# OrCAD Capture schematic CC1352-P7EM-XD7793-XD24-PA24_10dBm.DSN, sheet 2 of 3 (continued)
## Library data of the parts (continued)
L14 L52 L61 = INDUCTOR_HOR_1_2: INDUCTOR, RF, CHIP, NON-MAGNETIC CORE, 2nH, -0.3nH/+0.3nH, 0.3A, -55DEGC/+125DEGC, 0402, SMD; Additional Datasheet URL: https://search.murata.co.jp/Ceramy/image/img/P02/JELF243B-0010.pdf; AutoDoc File: https://notefied-dynamic-precision.com/DB/Apps/Desktop/Item/Object.aspx?id=113364; BU Name: TEXAS INSTRUMENTS NORWAY; Budget Currency: EUR; Budget Price: 0.031; Budgetary Price: 0.01872 USD; Client Status: UNDER_REVIEW; Core Material: NON-MAGNETIC; Country of Origin: Japan,Singapore; Datasheet URL: https://www.murata.com/-/media/webrenewal/support/library/catalog/products/inductor/chip/o05e.ashx?la=en-gb; Datasheet URL 1: http://psearch.murata.com/inductor/product/LQG15HS2N0S02%23.pdf; Datasheet URL 2: http://www.murata.com/~/media/webrenewal/support/library/catalog/products/inductor/chip/o05e.ashx; Exclusive for Customers: TEXAS INSTRUMENTS NORWAY; Frequency: 6GHz; Lead Time: 8; Mass: 0.001g; Max Oper Temp: +125DEGC; Max Tol: +0.3nH; Maximum Operating Temperature: +125DEGC; Maximum Tolerance: +0.3nH; Min Oper Temp: -55DEGC; Min Tol: -0.3nH; Minimum Operating Temperature: -55DEGC; Minimum Tolerance: -0.3nH; Mounting Type: SMD; NOTEfied URL: https://notefied-dynamic-precision.com/NOTEfiedWebInterface/part/show?partNumber=03-07527; Notes: Standard item: Duplicate Reason: custom footprint for TEXAS INSTRUMENTS NORWAY.; PCB Package: 0402; Packing Size: 10000; Packing Type: Tape & Reel; Part Number: 03-07527; Part Type: Inductor|RF|CHIP|0402; REACH/SVHC Compliance: Compliant; REACH/SVHC Details: SVHC List Version Jul 7, 2017; REACH/SVHC Source: REACH Declaration; REACH/SVHC Status: Unaffected; REACH/SVHC_COMPLIANCE: COMPLIANT; REACH/SVHC_DETAILS: SVHC LIST VERSION Dec 17, 2015; REACH/SVHC_SOURCE: REACH DECLARATION; REACH/SVHC_STATUS: UNAFFECTED; ROHS: Compliant; Revision: R023; RoHS Status: ROHS_COMPLIANT; Rtd Current: 0.3A; Status: Released; Texas Part Status: Under Review; Type: Inductor; Vendor: MURATA; Vendor Part Number: LQG15HS2N0S02D; Vendor Part Status: Active; Weight: 0.001g
L31 L41 = INDUCTOR_HOR_1_2: INDUCTOR, RF, CHIP, NON-MAGNETIC CORE, 3.9nH, -0.3nH/+0.3nH, 0.3A, -55DEGC/+125DEGC, 0402, SMD; ALT_SYMBOLS: INDC1005X60C2L,INDC1005X60C2M; Additional Datasheet URL: https://search.murata.co.jp/Ceramy/image/img/P02/JELF243B-0010.pdf; Budgetary Price: 0.01872 USD; Country of Origin: Japan,Singapore; Datasheet URL: https://www.murata.com/-/media/webrenewal/support/library/catalog/products/inductor/chip/o05e.ashx?la=en-gb; FPLIST: INDC1005X60C2N,INDC1005X60D2N; Frequency: 6GHz; Lead Time: 8; Mass: 0.001g; Maximum Operating Temperature: +125DEGC; Maximum Tolerance: +0.3nH; Minimum Operating Temperature: -55DEGC; Minimum Tolerance: -0.3nH; Mounting Type: SMD; NOTEfied URL: https://notefied-dynamic-precision.com/NOTEfiedWebInterface/part/show?partNumber=03-06630; PCB Package: 0402; Packing Size: 10000; Packing Type: Tape & Reel; Part Number: 03-06630; Part Type: Inductor|RF|CHIP|0402; REACH/SVHC Compliance: Compliant; REACH/SVHC Details: SVHC List Version Jul 7, 2017; REACH/SVHC Source: REACH Declaration; REACH/SVHC Status: Unaffected; ROHS: Compliant; Resistance: 0.18; Revision: R022; Status: Released; Texas Part Status: Under Review; Type: Inductor; Vendor: MURATA; Vendor Part Number: LQG15HS3N9S02D; Vendor Part Status: Active
L32 = INDUCTOR_HOR_1_2: INDUCTOR, RF, CHIP, NON-MAGNETIC CORE, 22nH, -5%/+5%, 0.3A, -55DEGC/+125DEGC, 0402, SMD; Additional Datasheet URL: https://search.murata.co.jp/Ceramy/image/img/P02/JELF243B-0010.pdf; AutoDoc File: https://notefied-dynamic-precision.com/DB/Apps/Desktop/Item/Object.aspx?id=113365; BU Name: TEXAS INSTRUMENTS NORWAY; Budget Currency: EUR; Budget Price: 0.03; Budgetary Price: 0.01872 USD; Client Status: UNDER_REVIEW; Core Material: NON-MAGNETIC; Country of Origin: Japan,Singapore; Datasheet URL: https://www.murata.com/-/media/webrenewal/support/library/catalog/products/inductor/chip/o05e.ashx?la=en-gb; Datasheet URL 1: http://psearch.murata.com/inductor/product/LQG15HS27NJ02%23.pdf; Datasheet URL 2: http://www.murata.com/~/media/webrenewal/support/library/catalog/products/inductor/chip/o05e.ashx; Exclusive for Customers: TEXAS INSTRUMENTS NORWAY; Frequency: 1900MHz; Lead Time: 8; Mass: 0.001g; Max Oper Temp: +125DEGC; Max Tol: +5%; Maximum Operating Temperature: +125DEGC; Maximum Tolerance: +5%; Min Oper Temp: -55DEGC; Min Tol: -5%; Minimum Operating Temperature: -55DEGC; Minimum Tolerance: -5%; Mounting Type: SMD; NOTEfied URL: https://notefied-dynamic-precision.com/NOTEfiedWebInterface/part/show?partNumber=03-07529; Notes: Standard item: Duplicate Reason: custom footprint for TEXAS INSTRUMENTS NORWAY.; PCB Package: 0402; Packing Size: 10000; Packing Type: Tape & Reel; Part Number: 03-07529; Part Type: Inductor|RF|CHIP|0402; REACH/SVHC Compliance: Compliant; REACH/SVHC Details: SVHC List Version Jul 7, 2017; REACH/SVHC Source: REACH Declaration; REACH/SVHC Status: Unaffected; REACH/SVHC_COMPLIANCE: COMPLIANT; REACH/SVHC_DETAILS: SVHC LIST VERSION Dec 17, 2015; REACH/SVHC_SOURCE: REACH DECLARATION; REACH/SVHC_STATUS: UNAFFECTED; ROHS: Compliant; Revision: R022; RoHS Status: ROHS_COMPLIANT; Rtd Current: 0.3A; Status: Released; Texas Part Status: Under Review; Type: Inductor; Vendor: MURATA; Vendor Part Number: LQG15HS22NJ02D; Vendor Part Status: Active; Weight: 0.001g
L33 L42 = INDUCTOR_HOR_1_2: INDUCTOR, RF, CHIP, NON-MAGNETIC CORE, 10nH, -5%/+5%, 0.3A, -55DEGC/+125DEGC, 0402, SMD; ALT_SYMBOLS: INDC1005X60C2L,INDC1005X60C2M; Additional Datasheet URL: https://search.murata.co.jp/Ceramy/image/img/P02/JELF243B-0010.pdf; AutoDoc File: https://notefied-dynamic-precision.com/DB/Apps/Desktop/Item/Object.aspx?id=113370; BU Name: TEXAS INSTRUMENTS NORWAY; Budget Currency: EUR; Budget Price: 0.03; Budgetary Price: 0.01872 USD; Client Status: UNDER_REVIEW; Core Material: NON-MAGNETIC; Country of Origin: Japan,Singapore; Datasheet URL: https://www.murata.com/-/media/webrenewal/support/library/catalog/products/inductor/chip/o05e.ashx?la=en-gb; Datasheet URL 1: http://psearch.murata.com/inductor/product/LQG15HS7N5J02%23.pdf; Datasheet URL 2: http://www.murata.com/~/media/webrenewal/support/library/catalog/products/inductor/chip/o05e.ashx; FPLIST: INDC1005X60C2N,INDC1005X60D2N; Frequency: 3.4GHz; Lead Time: 8; Mass: 0.001g; Max Oper Temp: +125DEGC; Max Tol: +5%; Maximum Operating Temperature: +125DEGC; Maximum Tolerance: +5%; Min Oper Temp: -55DEGC; Min Tol: -5%; Minimum Operating Temperature: -55DEGC; Minimum Tolerance: -5%; Mounting Type: SMD; NOTEfied URL: https://notefied-dynamic-precision.com/NOTEfiedWebInterface/part/show?partNumber=03-06635; PCB Package: 0402; Packing Size: 10000; Packing Type: Tape & Reel; Part Number: 03-06635; Part Type: Inductor|RF|CHIP|0402; REACH/SVHC Compliance: Compliant; REACH/SVHC Details: SVHC List Version Jul 7, 2017; REACH/SVHC Source: REACH Declaration; REACH/SVHC Status: Unaffected; REACH/SVHC_COMPLIANCE: COMPLIANT; REACH/SVHC_DETAILS: SVHC LIST VERSION Dec 17, 2015; REACH/SVHC_SOURCE: REACH DECLARATION; REACH/SVHC_STATUS: UNAFFECTED; ROHS: Compliant; Resistance: 0.26; Revision: R021; RoHS Status: ROHS_COMPLIANT; Rtd Current: 0.3A; Status: Released; Texas Part Status: Under Review; Type: Inductor; Vendor: MURATA; Vendor Part Number: LQG15HS10NJ02D; Vendor Part Status: Active; Weight: 0.001g
L34 = INDUCTOR_HOR_1_2: INDUCTOR, RF, CHIP, NON-MAGNETIC CORE, 7.5nH, -5%/+5%, 0.3A, -55DEGC/+125DEGC, 0402, SMD; Additional Datasheet URL: https://search.murata.co.jp/Ceramy/image/img/P02/JELF243B-0010.pdf; AutoDoc File: https://notefied-dynamic-precision.com/DB/Apps/Desktop/Item/Object.aspx?id=113369; BU Name: TEXAS INSTRUMENTS NORWAY; Budget Currency: EUR; Budget Price: 0.03; Budgetary Price: 0.01872 USD; Client Status: UNDER_REVIEW; Core Material: NON-MAGNETIC; Country of Origin: Missing Info; Datasheet URL: https://www.murata.com/-/media/webrenewal/support/library/catalog/products/inductor/chip/o05e.ashx?la=en-gb; Datasheet URL 1: http://psearch.murata.com/inductor/product/LQG15HS6N8J02%23.pdf; Datasheet URL 2: http://www.murata.com/~/media/webrenewal/support/library/catalog/products/inductor/chip/o05e.ashx; Frequency: 4.2GHz; Lead Time: 8; Mass: 0.001g; Max Oper Temp: +125DEGC; Max Tol: +5%; Maximum Operating Temperature: +125DEGC; Maximum Tolerance: +5%; Min Oper Temp: -55DEGC; Min Tol: -5%; Minimum Operating Temperature: -55DEGC; Minimum Tolerance: -5%; Mounting Type: SMD; NOTEfied URL: https://notefied-dynamic-precision.com/NOTEfiedWebInterface/part/show?partNumber=03-07022; PCB Package: 0402; Packing Size: 10000; Packing Type: Tape & Reel; Part Number: 03-07022; Part Type: Inductor|RF|CHIP|0402; REACH/SVHC Compliance: Compliant; REACH/SVHC Details: SVHC List Version Jul 7, 2017; REACH/SVHC Source: REACH Declaration; REACH/SVHC Status: Unaffected; REACH/SVHC_COMPLIANCE: COMPLIANT; REACH/SVHC_DETAILS: SVHC LIST VERSION Dec 17, 2015; REACH/SVHC_SOURCE: REACH DECLARATION; REACH/SVHC_STATUS: UNAFFECTED; ROHS: Compliant; Resistance: 0.24; Revision: R023; RoHS Status: ROHS_COMPLIANT; Rtd Current: 0.3A; Status: Released; Texas Part Status: Under Review; Type: Inductor; Vendor: MURATA; Vendor Part Number: LQG15HS7N5J02D; Vendor Part Status: Active; Weight: 0.001g
L53 = INDUCTOR_HOR_1_2: INDUCTOR, RF, NON-MAGNETIC CORE, 1.6nH, -0.3nH/+0.3nH, 1A, -55DEGC/+125DEGC, 0402, SMD; Additional Datasheet URL: https://search.murata.co.jp/Ceramy/image/img/P02/JELF243B-0010.pdf; AutoDoc File: https://notefied-dynamic-precision.com/DB/Apps/Desktop/Item/Object.aspx?id=116101; BU Name: TEXAS INSTRUMENTS NORWAY; Budget Currency: EUR; Budget Price: 0.031; Budgetary Price: 0.01872 USD; Client Status: UNDER_REVIEW; Core Material: NON-MAGNETIC; Datasheet URL: https://www.murata.com/-/media/webrenewal/support/library/catalog/products/inductor/chip/o05e.ashx?la=en-gb; Datasheet URL 1: http://psearch.murata.com/inductor/product/LQG15HS1N8S02%23.pdf; Datasheet URL 2: http://www.murata.com/~/media/webrenewal/support/library/catalog/products/inductor/chip/o05e.ashx; Frequency: 6GHz; Lead Time: 8; Mass: 0.001g; Max Oper Temp: +125DEGC; Max Tol: +0.3nH; Maximum Operating Temperature: +125DEGC; Maximum Tolerance: +0.3nH; Min Oper Temp: -55DEGC; Min Tol: -0.3nH; Minimum Operating Temperature: -55DEGC; Minimum Tolerance: -0.3nH; Mounting Type: SMD; NOTEfied URL: https://notefied-dynamic-precision.com/NOTEfiedWebInterface/part/show?partNumber=03-07865; PCB Package: 0402; Packing Size: 10000; Packing Type: Tape & Reel; Part Number: 03-07865; Part Type: Inductor|RF|CHIP|0402; REACH/SVHC Compliance: Compliant; REACH/SVHC Details: SVHC List Version Jul 7, 2017; REACH/SVHC Source: REACH Declaration; REACH/SVHC Status: Unaffected; REACH/SVHC_COMPLIANCE: COMPLIANT; REACH/SVHC_DETAILS: SVHC LIST VERSION Jun 20, 2016; REACH/SVHC_SOURCE: REACH DECLARATION; REACH/SVHC_STATUS: UNAFFECTED; ROHS: Compliant; Resistance: 0.07; Revision: R013; RoHS Status: ROHS_COMPLIANT; Rtd Current: 0.3A; Status: Released; Texas Part Status: Under Review; Type: Inductor; Vendor: MURATA; Vendor Part Number: LQG15HS1N6S02D; Vendor Part Status: Active; Weight: 0.001g
L54 = INDUCTOR_HOR_1_2: INDUCTOR, RF, CHIP, NON-MAGNETIC CORE, 1nH, -0.3nH/+0.3nH, 0.3A, -55DEGC/+125DEGC, 0402, SMD; ALT_SYMBOLS: INDC1005X60C2L,INDC1005X60C2M; Additional Datasheet URL: https://search.murata.co.jp/Ceramy/image/img/P02/JELF243B-0010.pdf; AutoDoc File: https://notefied-dynamic-precision.com/DB/Apps/Desktop/Item/Object.aspx?id=116041; BU Name: TEXAS INSTRUMENTS NORWAY; Budget Currency: EUR; Budget Price: 0.031; Budgetary Price: 0.01872 USD; Client Status: UNDER_REVIEW; Core Material: NON-MAGNETIC; Country of Origin: Japan,Singapore; Datasheet URL: https://www.murata.com/-/media/webrenewal/support/library/catalog/products/inductor/chip/o05e.ashx?la=en-gb; Datasheet URL 1: http://psearch.murata.com/inductor/product/LQG15HS1N0S02%23.pdf; Datasheet URL 2: http://www.murata.com/~/media/webrenewal/support/library/catalog/products/inductor/chip/o05e.ashx; Frequency: 10GHz; Lead Time: 8; Mass: 0.001g; Max Oper Temp: +125DEGC; Max Tol: +0.3nH; Maximum Operating Temperature: +125DEGC; Maximum Tolerance: +0.3nH; Min Oper Temp: -55DEGC; Min Tol: -0.3nH; Minimum Operating Temperature: -55DEGC; Minimum Tolerance: -0.3nH; Mounting Type: SMD; NOTEfied URL: https://notefied-dynamic-precision.com/NOTEfiedWebInterface/part/show?partNumber=03-07676; PCB Package: 0402; Packing Size: 10000; Packing Type: Tape & Reel; Part Number: 03-07676; Part Type: Inductor|RF|CHIP|0402; REACH/SVHC Compliance: Compliant; REACH/SVHC Details: SVHC List Version Jul 7, 2017; REACH/SVHC Source: REACH Declaration; REACH/SVHC Status: Unaffected; REACH/SVHC_COMPLIANCE: COMPLIANT; REACH/SVHC_DETAILS: SVHC LIST VERSION Jun 20, 2016; REACH/SVHC_SOURCE: REACH DECLARATION; REACH/SVHC_STATUS: UNAFFECTED; ROHS: Compliant; Resistance: 0.07; Revision: R024; RoHS Status: ROHS_COMPLIANT; Rtd Current: 0.3A; Status: Released; Texas Part Status: Under Review; Type: Inductor; Vendor: MURATA; Vendor Part Number: LQG15HS1N0S02D; Vendor Part Status: Active; Weight: 0.001g
L331 = INDUCTOR: INDUCTOR, STANDARD, FERRITE CORE, 6.8uH, -20%/+20%, 0.11A, -55DEGC/+125DEGC, 0805, SMD; ALT_SYMBOLS: INDC2012X150A2L,INDC2012X150A2M; Additional Datasheet URL: https://product.tdk.com/en/search/inductor/inductor/smd/info?part_no=MLZ2012N6R8LT000; AutoDoc File: https://notefied-dynamic-precision.com/DB/Apps/Desktop/Item/Object.aspx?id=102853; BU Name: DYNAMIC PRECISION GDANSK; Budget Currency: EUR; Budget Price: 0.059; Budgetary Price: 0.045 USD; Client Status: UNDER_REVIEW; Core Material: FERRITE; Country of Origin: Missing Info; Datasheet URL: http://product.tdk.com/info/en/catalog/datasheets/inductor_commercial_decoupling_mlz2012_en.pdf; Datasheet URL 1: https://product.tdk.com/info/en/catalog/datasheets/inductor_commercial_decoupling_mlz2012_en.pdf; Datasheet URL 2: N/A; Lead Time: 10; MPN: MLZ2012N6R8LT000; MPN Status: ACTIVE; Manufacturer: TDK; Mass: 0.01g; Max Oper Temp: +125DEGC; Max Tol: +20%; Maximum Operating Temperature: +125DEGC; Maximum Tolerance: +20%; Min Oper Temp: -55DEGC; Min Tol: -20%; Minimum Operating Temperature: -55DEGC; Minimum Tolerance: -20%; Mounting Type: SMD; NOTE Status: PREFERRED; NOTEfied URL: https://notefied-dynamic-precision.com/NOTEfiedWebInterface/part/show?partNumber=03-07266; Old Footprint: INDC2012X150N; PCB Package: 0805; Packing Size: 4000; Packing Type: Tape & Reel; Part Number: 03-07266; Part Type: Inductor|STANDARD|CHIP|0805; REACH/SVHC Compliance: Compliant; REACH/SVHC Details: SVHC List Version Jan 12, 2017; REACH/SVHC Source: REACH Declaration; REACH/SVHC Status: Unaffected; REACH/SVHC_COMPLIANCE: COMPLIANT; REACH/SVHC_DETAILS: SVHC LIST VERSION Dec 17, 2015; REACH/SVHC_SOURCE: REACH DECLARATION; REACH/SVHC_STATUS: UNAFFECTED; ROHS: Compliant; Resistance: 0.25; Revision: R019; RoHS Status: ROHS_COMPLIANT; Rtd Current: 1.1A; Status: Released; Texas Part Status: Under Review; Type: Inductor; Vendor: TDK; Vendor Part Number: MLZ2012N6R8LT000; Vendor Part Status: Active; WEIGHT: 0.01g
P1 P2 = CONN_HEADER_2X10_P_S: CONNECTOR, HEADER, FEMALE, STRAIGHT, 2 ROWS, 20 PINS, PITCH 1.27mm, SMD; ALT_SYMBOLS: SAMTEC_SFM11002AL,SAMTEC_SFM11002AM; Additional Datasheet URL: http://suddendocs.samtec.com/prints/sfm-1xx-xx-xxx-d-xxx-mkt.pdf; Alt IPC Footprints: SAMTEC_SFM11002AL,SAMTEC_SFM11002AM; AutoDoc File: https://notefied-dynamic-precision.com/DB/Apps/Desktop/Item/Object.aspx?id=85603; BU Name: TEXAS INSTRUMENTS NORWAY; Budget Currency: USD; Budget Price: 3.180; Budgetary Price: 5.3504 USD; CLASS: IO; Client Status: UNDER_REVIEW; Country of Origin: China,Costa Rica,Malaysia,Singapore,United States; Datasheet URL: http://suddendocs.samtec.com/catalog_english/sfm.pdf; Datasheet URL 1: http://suddendocs.samtec.com/catalog_english/sfm.pdf; Datasheet URL 2: http://suddendocs.samtec.com/prints/sfm-1xx-xx-xxx-d-xxx-mkt.pdf; MPN: SFM-110-02-SM-D-A-K-TR; MPN Status: ACTIVE; Manufacturer: SAMTEC; Mass: 0.30875g; Max Oper Temp: +125DEGC; Maximum Operating Temperature: +125DEGC; Min Oper Temp: -55DEGC; Minimum Operating Temperature: -55DEGC; Mounting Type: SMD; NOTE Status: PREFERRED; NOTEfied URL: https://notefied-dynamic-precision.com/NOTEfiedWebInterface/part/show?partNumber=06-02251; No Of Pos: 20; No Of Rows: 2; Number of Positions: 20; Number of Rows: 2; Packing Size: 725; Packing Type: Tape & Reel; Part Number: 06-02251; Part Type: Connector|HEADER|STANDARD; Pitch: 1.27mm; REACH/SVHC Compliance: Compliant; REACH/SVHC Details: SVHC List Version Jan 12, 2017; REACH/SVHC Source: Material Declaration; REACH/SVHC Status: Unaffected; ROHS: Compliant; Revision: R017; RoHS Status: ROHS_COMPLIANT; Status: Released; Texas Part Status: Under Review; Type: Connector; Vendor: SAMTEC; Vendor Part Number: SFM-110-02-SM-D-A-K-TR; Vendor Part Status: Active; Weight: 0.30875g
R1 R2 = RESISTOR: RESISTOR, THICK FILM, 0, 0R/+0.008R, 0.33W, 5A, -55DEGC/+155DEGC, 0603, SMD; ALT_SYMBOLS: RESC1608X55A2L,RESC1608X55A2M; Additional Datasheet URL: N/A; AutoDoc File: https://notefied-dynamic-precision.com/DB/Apps/Desktop/Item/Object.aspx?id=86391; BU Name: DYNAMIC PRECISION GDANSK; Budget Currency: EUR; Budget Price: 0.007; Budgetary Price: 0.034 EUR; Client Status: UNDER_REVIEW; Country of Origin: Israel; Datasheet URL: https://www.vishay.com/docs/20043/crcwhpe3.pdf; Datasheet URL 1: http://www.vishay.com/docs/20035/dcrcwe3.pdf; Datasheet URL 2: N/A; Definied Quality: INDUSTRIAL; Esd Level: N/A; Lead Time: 14; LifeCycle Status: ACTIVE; MPN: RESISTOR_0402_0_+/-5%_50V_0.063W_M_+/-200PPM; MPN Status: ACTIVE; MSL: N/A; MTBF: N/A; MTBF Standard: N/A; Manufacturer: MANUFACTURER SELECTION; Mass: 0.002g; Max Oper Temp: +155DEGC; Max TC: N/A; Max Tol: N/A; Maximum Operating Temperature: +155DEGC; Maximum Temperature Coefficient: N/A; Maximum Tolerance: +0.008R; Min Oper Temp: -55DEGC; Min TC: N/A; Min Tol: N/A; Minimum Operating Temperature: -55DEGC; Minimum Temperature Coeficient: N/A; Minimum Tolerance: 0R; Mounting Type: SMD; NOTE Status: PREFERRED; NOTEfied URL: https://notefied-dynamic-precision.com/NOTEfiedWebInterface/part/show?partNumber=01-16898; Old Footprint: RESC1005X40N; PCB Package: 0603; Packing Size: 5000; Packing Type: Tape & Reel; Part Number: 01-16898; Part Type: Resistor|0603|JUMPER; ROHS: Exempt; Rated Current: 5A; Rated Power: 0.33W; Rated Voltage: N/A; Resistor Type: THICK FILM; Revision: R026; RoHS Status: ROHS_COMPLIANT_WITH_EXEMPTION; Rtd Current: N/A; Rtd Power: 0.063W; Rtd Voltage: 50V; Status: Released; Type: Resistor; Vendor: VISHAY; Vendor Part Number: CRCW06030000Z0EAHP; Vendor Part Status: Active; WEIGHT: 0.0006152g
R351 = RESISTOR: RESISTOR, THICK FILM, 100k, -5%/+5%, 0.063W, 50V, -55DEGC/+155DEGC, 0402, SMD; Additional Datasheet URL: N/A; AutoDoc File: https://notefied-dynamic-precision.com/DB/Apps/Desktop/Item/Object.aspx?id=114565; BU Name: TEXAS INSTRUMENTS NORWAY; Budget Currency: EUR; Budget Price: 0.014; Budgetary Price: 0.014 EUR; Client Status: UNDER_REVIEW; Country of Origin: United States; Datasheet URL: https://www.vishay.com/docs/20035/dcrcwe3.pdf; Datasheet URL 1: http://www.vishay.com/docs/20035/dcrcwe3.pdf; Datasheet URL 2: N/A; Definied Quality: INDUSTRIAL; Esd Level: N/A; Exclusive for Customers: TEXAS INSTRUMENTS NORWAY; Lead Time: 18; LifeCycle Status: ACTIVE; MPN: RESISTOR_0402_100k_+/-1%_50V_0.063W_M_+/-100PPM; MPN Status: ACTIVE; MSL: N/A; MTBF: N/A; MTBF Standard: N/A; Manufacturer: MANUFACTURER SELECTION; Mass: 0.00065g; Max Oper Temp: +155DEGC; Max TC: +200PPM/DEGC; Max Tol: +5%; Maximum Operating Temperature: +155DEGC; Maximum Temperature Coefficient: +200PPM/DEGC; Maximum Tolerance: +5%; Min Oper Temp: -55DEGC; Min TC: -200PPM/DEGC; Min Tol: -5%; Minimum Operating Temperature: -55DEGC; Minimum Temperature Coeficient: -200PPM/DEGC; Minimum Tolerance: -5%; Mounting Type: SMD; NOTE Status: PREFERRED; NOTEfied URL: https://notefied-dynamic-precision.com/NOTEfiedWebInterface/part/show?partNumber=01-22492; Notes: Standard item: Duplicate Reason: custom footprint for TEXAS INSTRUMENTS NORWAY.; Old Footprint: RESC1005X40N; PCB Package: 0402; Packing Size: 10000; Packing Type: Tape & Reel; Part Number: 01-22492; Part Type: Resistor|0402|STANDARD; REACH/SVHC Compliance: Compliant; REACH/SVHC Details: SVHC List Version Jun 20, 2016; REACH/SVHC Source: Material Declaration; REACH/SVHC Status: Unaffected; REACH/SVHC_COMPLIANCE: COMPLIANT; REACH/SVHC_DETAILS: SVHC LIST VERSION Jun 20, 2016; REACH/SVHC_SOURCE: MATERIAL DECLARATION; REACH/SVHC_STATUS: UNAFFECTED; ROHS: Exempt; Rated Current: N/A; Rated Power: 0.063W; Rated Voltage: 50V; Resistor Type: THICK FILM; Revision: R019; RoHS Status: ROHS_COMPLIANT; Rtd Current: N/A; Rtd Power: 0.063W; Rtd Voltage: 50V; Status: Released; Texas Part Status: Under Review; Type: Resistor; Vendor: VISHAY; Vendor Part Number: CRCW0402100KJNED; Vendor Part Status: Active; WEIGHT: 0.00065g
U1 = IC_RF_CC1352P1F64_QFN48: IC, MICROCONTROLLER, TEXAS INSTRUMENTS, ARM CORTEX M4F, HIGH-PERFORMANCE DUAL-BAND WIRELESS MCU WITH INTEGRATED POWER AMPLIFIER, 1.8V TO 3.8V, VQFN48-EP, SMD; ALT_SYMBOLS: QFNFC50P700X700X100-49A2L,QFNFC50P700X700X100-49A2M; Additional Datasheet URL: N/A; Datasheet URL: https://www.ti.com/; Exclusive for Customers: TEXAS INSTRUMENTS NORWAY; Frequency: 48MHz; Mass: N/A; Maximum Operating Temperature: +85DEGC; Minimum Operating Temperature: -40DEGC; Mounting Type: SMD; NOTEfied URL: https://notefied-dynamic-precision.com/NOTEfiedWebInterface/part/show?partNumber=18-36101; Notes: Preliminary item, please check if it apperas on the website.; PCB Package: VQFN48-EP; Packing Size: N/A; Packing Type: Missing Info; Part Number: 18-36101; Part Type: IC|MICROCONTROLLER|TEXAS INSTRUMENTS; REACH/SVHC Compliance: Missing Info; REACH/SVHC Details: N/A; REACH/SVHC Source: N/A; REACH/SVHC Status: Missing Info; ROHS: Compliant; Rated Voltage: 1.8V TO 3.8V; Revision: R003; Status: Released; Texas Part Status: Under Review; Type: IC; Vendor: TEXAS INSTRUMENTS; Vendor Part Status: Preliminary
Y1 = XTAL: CRYSTAL, RESONATOR, 32.768kHz, -40DEGC/+125DEGC, SMD; ALT_SYMBOLS: XTAL_TZ1166C_B2L,XTAL_TZ1166C_B2M; Additional Datasheet URL: N/A; Capacitance: 7pF; Datasheet URL: https://www.taisaw.com/en/product.php?pc=7; Exclusive for Customers: TEXAS INSTRUMENTS NORWAY; Mass: N/A; Maximum Operating Temperature: +125DEGC; Maximum Stability: N/A; Maximum Tolerance: +20PPM; Minimum Operating Temperature: -40DEGC; Minimum Stability: N/A; Minimum Tolerance: -20PPM; Mounting Type: SMD; NOTEfied URL: https://notefied-dynamic-precision.com/NOTEfiedWebInterface/part/show?partNumber=12-01495; Notes: Non-standard part/non-catalogue part. Created on the basis of documentation provided by the customer (Texas Instruments).; Packing Size: 3000; Packing Type: Tape & Reel; Part Number: 12-01495; Part Type: Crystal|RESONATOR; REACH/SVHC Compliance: Missing Info; REACH/SVHC Details: N/A; REACH/SVHC Source: N/A; REACH/SVHC Status: Missing Info; ROHS: Compliant; Revision: R002; Status: Released; Texas Part Status: Under Review; Type: Crystal; Vendor: TAI-SAW; Vendor Part Number: TZ1166C; Vendor Part Status: Active
Y2 = XTAL_4_V3: CRYSTAL, RESONATOR, 48MHz, -16PPM/+16PPM, -40DEGC/+105DEGC, SMD; ALT_SYMBOLS: OSCCC200X160X50-4A2L,OSCCC200X160X50-4A2M; Capacitance: 7pF; Datasheet URL: https://www.taisaw.com/en/product.php?pc=7; Exclusive for Customers: TEXAS INSTRUMENTS NORWAY; Mass: 0.0057g; Maximum Operating Temperature: +105DEGC; Maximum Stability: +16PPM; Maximum Tolerance: +8PPM; Minimum Operating Temperature: -40DEGC; Minimum Stability: -16PPM; Minimum Tolerance: -8PPM; Mounting Type: SMD; NOTEfied URL: https://notefied-dynamic-precision.com/NOTEfiedWebInterface/part/show?partNumber=12-01494; Notes: Non-standard part/non-catalogue part. Created on the basis of documentation provided by the customer (Texas Instruments).; Packing Size: 3000; Packing Type: Tape & Reel; Part Number: 12-01494; Part Type: Crystal|RESONATOR; REACH/SVHC Compliance: Missing Info; REACH/SVHC Details: N/A; REACH/SVHC Source: N/A; REACH/SVHC Status: Missing Info; ROHS: Compliant; Revision: R001; Status: Released; Texas Part Status: Under Review; Type: Crystal; Vendor: TAI-SAW; Vendor Part Number: TZ2365C; Vendor Part Status: Active

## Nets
GND: BAT-1.1 BT1.3(-) C1.2 C2.2 C11.2 C13.2 C14.2 C21.2 C32.2 C34.2 C35.1 C41.1 C51.1 C52.2 C54.2 C55.2 C56.2 C61.1 C81.2 C91.2 C131.2 C221.2 C231.2 C331.2 C341.2 C342.2 C351.2 C441.2 C451.2 C461.2 C471.2 C481.2 J1.2 J1.3 J1.4 J1.5 J2.2 J2.3 J2.4 J2.5 J3.2 J3.3 J3.4 J3.5 P1.1 P1.19 P2.2 P2.20 U1.49(EGP) Y2.2(GND) Y2.4(GND) ; also on sheet 1
VDD_EB: FL1.2 P2.7 P2.9 R2.2
VDDR: C51.2 C52.1 C331.1 C451.1 C481.1 L52.1 L331.2 U1.45(VDDR) U1.48(VDDR_RF)
VDDS: C1.1 C2.1 C131.1 C221.1 C341.1 C342.1 C441.1 FL1.1 R351.2 U1.13(VDDS2) U1.22(VDDS3) U1.34(VDDS_DCDC) U1.44(VDDS)
DCDC_SW: L331.1 U1.33(DCDC_SW)
DIO_5: P1.13 U1.10(DIO_5)
DIO_6: P1.4 U1.11(DIO_6)
DIO_7: P1.2 U1.12(DIO_7)
DIO_8: P1.20 U1.14(DIO_8)
DIO_9: P1.18 U1.15(DIO_9)
DIO_10: P1.16 U1.16(DIO_10)
DIO_11: P1.14 U1.17(DIO_11)
DIO_12: P1.12 U1.18(DIO_12)
DIO_13: P1.15 U1.19(DIO_13)
DIO_14: P1.17 U1.20(DIO_14)
DIO_15: P1.6 U1.21(DIO_15)
DIO_16 / JTAG TDO: P2.19 U1.26(DIO_16)
DIO_17 / JTAG TDI: P2.17 U1.27(DIO_17)
DIO_18: P1.7 U1.28(DIO_18)
DIO_19: P1.9 U1.29(DIO_19)
DIO_20: P2.8 U1.30(DIO_20)
DIO_21: P2.18 U1.31(DIO_21)
DIO_22: P1.3 U1.32(DIO_22)
DIO_23: P2.5 U1.36(DIO_23)
DIO_24: P2.10 U1.37(DIO_24)
DIO_25: P2.11 U1.38(DIO_25)
DIO_26: P2.6 U1.39(DIO_26)
DIO_27: P2.13 U1.40(DIO_27)
DIO_28: P2.16 U1.41(DIO_28)
DIO_29: P2.14 U1.42(DIO_29)
DIO_30: P2.12 U1.43(DIO_30)
JTAG_TCK: P2.1 U1.25(JTAG_TCKC)
JTAG_TMS: P2.4 U1.24(JTAG_TMSC)
nRESET: C351.1 P2.15 R351.1 U1.35(RESET_N)
RX_TX: C11.1 C32.1 L12.1 L33.1 U1.7(RX_TX)
N485531: C36.1 J1.1
N485663: C33.2 C34.1 L34.1 L42.2
N485675: C35.2 C36.2 L34.2
N485699: C231.1 U1.23(DCOUPL)
N485705: C81.1 U1.8(X32K_Q1) Y1.1
N485903: C31.1 C33.1 L31.2 L32.1 L33.2
N501936: C471.1 U1.47(X48M_P) Y2.1
N501950: C461.1 U1.46(X48M_N) Y2.3
N510840: C12.1 L11.1 L12.2 U1.1(2_4_GHZ_RF_P)
N510850: C21.1 L11.2 L21.1 U1.2(2_4_GHZ_RF_N)
N512042: C13.1 L13.2 L14.1
N512564: C15.2 J2.1
N514814: C12.2 L13.1 L21.2
N516767: C31.2 C41.2 L32.2 L41.2 L42.1
N517777: C61.2 L51.2 L61.1 U1.6(TX_20DBM_N)
N517785: C53.1 L51.1 L52.2 U1.5(TX_20DBM_P)
N517815: C53.2 C54.1 L53.1 L61.2
N517942: C55.1 L53.2 L54.1
N518069: C56.1 C57.1 L54.2
N520038: C57.2 J3.1
N520167: L41.1 U1.4(SUB-1_GHZ_RF_N)
N553230: C14.1 C15.1 L14.2
N613500: L31.1 U1.3(SUB-1_GHZ_RF_P)
N621290: C91.1 U1.9(X32K_Q2) Y1.2
N2095591: BAT+1.1 R1.1
N2095595: BT1.1(+) BT1.2(+) R1.2 R2.1

Not connected (* = marked no-connect by the designer): P1 5* 8* 10* 11*; P2 3*

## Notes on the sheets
sheet 2
- VDDS Decoupling Capacitors
- VDDR Decoupling Capacitors
- Pin 13
- Pin 22
- Pin 44
- Pin 34
- Pin 45
- Pin 48
- Place L331 and C331 close to pin 33.
  Low inductance ground for C331
- 5dBm 2.4GHz output
- 14dBm 770MHz-930MHz output
- 10dBm 2.4GHz output
- EM connector 1
- EM connector 2
